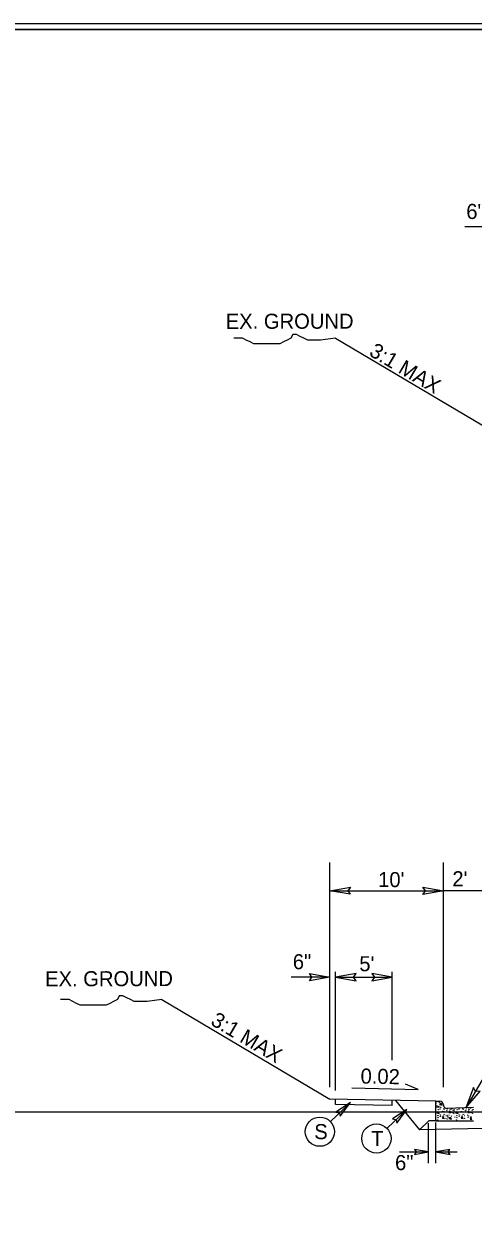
# Model space of a CAD drawing. Extents: x 2320980 to 2456309, y 595047 to 606177.
# Drawn here: x 2455793.4 to 2455833, y 596851.5 to 596956.6 of the extents above; entities that cross this region are included whole.
import ezdxf

# ---------------------------------------------------------------- set-up
doc = ezdxf.new("R2010")
doc.units = 0
for name, color, linetype in [('Default', 7, 'Continuous'), ('Old_Level_1', 7, 'Continuous'), ('Old_Level_20', 7, 'Continuous'), ('Old_Level_21', 7, 'Continuous'), ('Prop Dimension Text', 7, 'Continuous'), ('Sheet Cutting Line CELL', 7, 'Continuous'), ('Sheet Plan CELL', 7, 'Continuous'), ('Sheet Plot Border Inside CELL', 7, 'Continuous'), ('Typical Berm CELL', 7, 'Continuous'), ('Typical Curb CELL', 7, 'Continuous'), ('Typical Hinge Slope Arterial CELL', 7, 'Continuous'), ('Typical ID Circle CELL', 7, 'Continuous'), ('Typical Pavement Slope CELL', 7, 'Continuous'), ('Typical Terminator CELL', 7, 'Continuous')]:
    doc.layers.add(name, color=color, linetype=linetype)

msp = doc.modelspace()

# ---------------------------------------------------------------- linework, layer by layer
at = {"layer": 'Old_Level_21'}
for p, q in [((2455835.65, 596938.66), (2455832.24, 596938.66)), ((2455820.85, 596928.85), (2455835.65, 596920.08)), ((2455820.36, 596862.79), (2455820.36, 596882.61)), ((2455830.36, 596878.87), (2455830.36, 596882.61)), ((2455820.36, 596880.11), (2455830.36, 596880.11)), ((2455848.02, 596880.11), (2455830.36, 596880.11)), ((2455830.36, 596862.79), (2455830.36, 596878.87)), ((2455820.86, 596862.48), (2455820.86, 596872.96)), ((2455825.86, 596865.17), (2455825.86, 596872.96)), ((2455820.36, 596872.49), (2455816.95, 596872.49)), ((2455820.86, 596872.49), (2455825.86, 596872.49)), ((2455805.56, 596870.51), (2455820.36, 596861.74)), ((2455829.06, 596856.07), (2455829.06, 596859.61)), ((2455829.69, 596856.07), (2455829.69, 596859.66))]:
    msp.add_line(p, q, dxfattribs=at)
at = {"layer": 'Prop Dimension Text'}
for p, q in [((2455820.41, 596859.76), (2455822.16, 596861.44)), ((2455825.39, 596859.15), (2455827.15, 596860.83)), ((2455826.5, 596857.08), (2455829.06, 596857.08)), ((2455829.69, 596857.08), (2455831.58, 596857.08))]:
    msp.add_line(p, q, dxfattribs=at)
msp.add_lwpolyline([(2455822.29, 596862.74), (2455828.15, 596862.58), (2455827.01, 596863.06)], dxfattribs=at)
for centre in [(2455819.47, 596858.86), (2455824.46, 596858.26)]:
    msp.add_circle(centre, 1.29, dxfattribs=at)
at = {"layer": 'Sheet Cutting Line CELL'}
msp.add_line((2456045.51, 596860.57), (2455708.81, 596860.57), dxfattribs=at)
at = {"layer": 'Sheet Plan CELL'}
for points in [[(2456042.11, 596956.08), (2455742.1, 596956.08), (2455742.1, 596746.08), (2456042.11, 596746.08)], [(2455742.1, 596746.08), (2455742.1, 596956.07), (2456002.1, 596956.08), (2456002.1, 596926.07), (2456042.11, 596926.06), (2456042.11, 596746.08)]]:
    msp.add_lwpolyline(points, close=True, dxfattribs=at)
at = {"layer": 'Sheet Plot Border Inside CELL'}
msp.add_lwpolyline([(2455711.41, 596745.57), (2456044.6, 596745.58), (2456044.61, 596956.57), (2455711.41, 596956.57)], close=True, dxfattribs=at)
at = {"layer": 'Typical Berm CELL'}
for p, q in [((2455829.69, 596861.55), (2455820.36, 596861.74)), ((2455829.69, 596859.83), (2455829.07, 596859.83))]:
    msp.add_line(p, q, dxfattribs=at)
at = {"layer": 'Typical Curb CELL'}
for p, q in [((2455829.69, 596859.83), (2455829.69, 596861.55)), ((2455829.69, 596861.55), (2455830.04, 596861.55)), ((2455829.74, 596861.05), (2455829.95, 596861.11)), ((2455829.95, 596861.11), (2455829.92, 596860.99)), ((2455830.16, 596861.35), (2455830.02, 596861.25)), ((2455830.02, 596861.25), (2455830.24, 596861.2)), ((2455830.24, 596861.2), (2455830.16, 596861.35)), ((2455830.36, 596861.22), (2455830.36, 596861.23)), ((2455829.92, 596860.99), (2455829.74, 596861.05)), ((2455829.91, 596860.62), (2455829.77, 596860.52)), ((2455829.77, 596860.52), (2455829.99, 596860.47)), ((2455829.99, 596860.47), (2455829.91, 596860.62)), ((2455830.32, 596860.19), (2455830.27, 596860.04)), ((2455830.43, 596860.03), (2455830.32, 596860.19)), ((2455833.02, 596861), (2455830.69, 596860.9)), ((2455830.89, 596860.7), (2455830.85, 596860.55)), ((2455830.85, 596860.55), (2455831.01, 596860.54)), ((2455830.99, 596860.11), (2455830.85, 596860.01)), ((2455831.01, 596860.54), (2455830.89, 596860.7)), ((2455831.07, 596859.96), (2455830.99, 596860.11)), ((2455831.57, 596860.62), (2455831.43, 596860.52)), ((2455831.43, 596860.52), (2455831.65, 596860.47)), ((2455831.65, 596860.47), (2455831.57, 596860.62)), ((2455831.98, 596860.19), (2455831.93, 596860.04)), ((2455832.09, 596860.03), (2455831.98, 596860.19)), ((2455832.56, 596860.7), (2455832.51, 596860.55)), ((2455832.51, 596860.55), (2455832.67, 596860.54)), ((2455832.67, 596860.54), (2455832.56, 596860.7)), ((2455832.77, 596860.1), (2455832.72, 596859.95)), ((2455832.88, 596859.94), (2455832.77, 596860.1)), ((2455829.69, 596859.83), (2455833.02, 596859.83)), ((2455830.27, 596860.04), (2455830.43, 596860.03)), ((2455830.85, 596860.01), (2455831.07, 596859.96)), ((2455831.93, 596860.04), (2455832.09, 596860.03)), ((2455832.72, 596859.95), (2455832.88, 596859.94))]:
    msp.add_line(p, q, dxfattribs=at)
for centre in [(2455829.71, 596861.4), (2455829.78, 596861.16), (2455830, 596861.45), (2455829.72, 596860.14), (2455829.88, 596860.28), (2455829.89, 596860.1), (2455829.91, 596860.8), (2455830.07, 596860.86), (2455830.09, 596860.21), (2455830.11, 596860.33), (2455830.12, 596861.01), (2455830.28, 596861.08), (2455830.3, 596860.65), (2455830.35, 596860.25), (2455830.41, 596860.9), (2455830.42, 596860.4), (2455830.43, 596860.84), (2455830.47, 596860.61), (2455830.55, 596860.03), (2455830.58, 596860.29), (2455830.66, 596860.24), (2455830.67, 596860.72), (2455830.7, 596860.86), (2455830.73, 596860.29), (2455830.76, 596860.16), (2455830.85, 596860.32), (2455830.96, 596860.8), (2455830.99, 596860.29), (2455831.06, 596860.23), (2455831.09, 596860.86), (2455831.13, 596860.54), (2455831.24, 596860.75), (2455831.26, 596860.48), (2455831.31, 596860.8), (2455831.33, 596860.67), (2455831.34, 596860.26), (2455831.39, 596860.14), (2455831.55, 596860.28), (2455831.55, 596860.1), (2455831.57, 596860.8), (2455831.73, 596860.86), (2455831.75, 596860.21), (2455831.77, 596860.33), (2455831.96, 596860.65), (2455832.01, 596860.25), (2455832.07, 596860.9), (2455832.09, 596860.4), (2455832.09, 596860.84), (2455832.13, 596860.61), (2455832.21, 596860.03), (2455832.24, 596860.29), (2455832.33, 596860.72), (2455832.37, 596860.86), (2455832.51, 596860.32), (2455832.54, 596860.12), (2455832.56, 596860.94), (2455832.56, 596860.24), (2455832.62, 596860.8), (2455832.72, 596860.23), (2455832.75, 596860.92), (2455832.79, 596860.54), (2455832.8, 596860.16), (2455832.9, 596860.75), (2455832.92, 596860.48), (2455832.97, 596860.8), (2455829.85, 596859.89), (2455830.68, 596859.97), (2455831.51, 596859.89)]:
    msp.add_circle(centre, 0.0107, dxfattribs=at)
for centre, start, end in [((2455830.04, 596861.23), 0, 90), ((2455830.68, 596861.22), 180, 272.3845)]:
    msp.add_arc(centre, 0.319, start, end, dxfattribs=at)
at = {"layer": 'Typical Hinge Slope Arterial CELL'}
for points in [[(2455820.85, 596928.85), (2455819.54, 596928.68), (2455819.22, 596928.68), (2455818.72, 596928.68), (2455818.4, 596928.68), (2455818.07, 596928.85), (2455817.74, 596929.01), (2455817.41, 596929.17), (2455817.09, 596929.17), (2455816.92, 596928.85), (2455816.59, 596928.68), (2455816.27, 596928.52), (2455815.94, 596928.35), (2455815.61, 596928.35), (2455815.28, 596928.35), (2455814.95, 596928.35), (2455814.63, 596928.35), (2455814.3, 596928.35), (2455813.97, 596928.35), (2455813.64, 596928.35), (2455813.32, 596928.52), (2455812.99, 596928.68), (2455812.66, 596928.85), (2455812.17, 596928.85), (2455811.9, 596928.85)], [(2455805.56, 596870.51), (2455804.25, 596870.34), (2455803.93, 596870.34), (2455803.43, 596870.34), (2455803.11, 596870.34), (2455802.78, 596870.51), (2455802.45, 596870.67), (2455802.12, 596870.84), (2455801.79, 596870.84), (2455801.63, 596870.51), (2455801.3, 596870.34), (2455800.97, 596870.18), (2455800.65, 596870.02), (2455800.32, 596870.02), (2455799.99, 596870.02), (2455799.66, 596870.02), (2455799.34, 596870.02), (2455799.01, 596870.02), (2455798.68, 596870.02), (2455798.35, 596870.02), (2455798.03, 596870.18), (2455797.7, 596870.34), (2455797.37, 596870.51), (2455796.88, 596870.51), (2455796.61, 596870.51)]]:
    msp.add_lwpolyline(points, dxfattribs=at)
at = {"layer": 'Typical ID Circle CELL'}
msp.add_line((2455834.57, 596864.78), (2455832.34, 596860.96), dxfattribs=at)
at = {"layer": 'Typical Pavement Slope CELL'}
for p, q in [((2455820.86, 596861.27), (2455820.86, 596861.73)), ((2455825.86, 596861.17), (2455820.86, 596861.27)), ((2455825.86, 596861.17), (2455825.86, 596861.63)), ((2455826.15, 596861.62), (2455828.26, 596859.02)), ((2455829.07, 596859.83), (2455828.26, 596859.02)), ((2455848.68, 596859.44), (2455828.26, 596859.03))]:
    msp.add_line(p, q, dxfattribs=at)
at = {"layer": 'Typical Terminator CELL'}
for points in [[(2455822.15, 596879.8), (2455820.36, 596880.11), (2455822.16, 596880.43), (2455821.93, 596880.11)], [(2455828.56, 596880.42), (2455830.36, 596880.11), (2455828.55, 596879.79), (2455828.78, 596880.11)], [(2455818.56, 596872.8), (2455820.36, 596872.49), (2455818.55, 596872.17), (2455818.78, 596872.49)], [(2455822.66, 596872.8), (2455820.86, 596872.49), (2455822.67, 596872.17), (2455822.44, 596872.49)], [(2455824.06, 596872.18), (2455825.86, 596872.49), (2455824.05, 596872.81), (2455824.28, 596872.49)], [(2455833.02, 596862.76), (2455832.34, 596860.96), (2455833.59, 596862.44), (2455833.18, 596862.4)], [(2455821.26, 596860.22), (2455822.16, 596861.44), (2455820.89, 596860.59), (2455821.21, 596860.53)], [(2455826.25, 596859.61), (2455827.15, 596860.83), (2455825.88, 596859.98), (2455826.2, 596859.92)], [(2455827.81, 596856.86), (2455829.06, 596857.08), (2455827.81, 596857.3), (2455827.96, 596857.08)], [(2455830.94, 596857.29), (2455829.69, 596857.08), (2455830.95, 596856.86), (2455830.79, 596857.08)]]:
    msp.add_lwpolyline(points, close=True, dxfattribs=at)

# ---------------------------------------------------------------- texts
at = {"layer": 'Default'}
for s, rotation, p in [('6"', 0.0002, (2455832.38, 596939.36)), ('6"', 0.0002, (2455817.09, 596873.19)), ("5'", 359.9998, (2455822.95, 596873.01))]:
    msp.add_text(s, height=1.33, rotation=rotation, dxfattribs=at).set_placement(p)
at = {"layer": 'Old_Level_1'}
for p in [(2455811.18, 596929.67), (2455795.26, 596871.68)]:
    msp.add_text('EX. GROUND', height=1.33, rotation=0.0897, dxfattribs=at).set_placement(p)
at = {"layer": 'Old_Level_20'}
for s, p in [('S', (2455818.98, 596858.2)), ('T', (2455824, 596857.59))]:
    msp.add_text(s, height=1.33, dxfattribs=at).set_placement(p)
at = {"layer": 'Old_Level_21'}
for s, rotation, p in [('3:1 MAX', 329.3616, (2455823.73, 596927.37)), ("2'", 359.9998, (2455831.15, 596880.5)), ('3:1 MAX', 329.3616, (2455809.76, 596868.35)), ('0.02', 358.8544, (2455823.05, 596863.11))]:
    msp.add_text(s, height=1.33, rotation=rotation, dxfattribs=at).set_placement(p)
for s, p in [("10'", (2455824.61, 596880.43)), ('6"', (2455826.1, 596855.47))]:
    msp.add_text(s, height=1.33, dxfattribs=at).set_placement(p)

doc.saveas('drawing.dxf')
